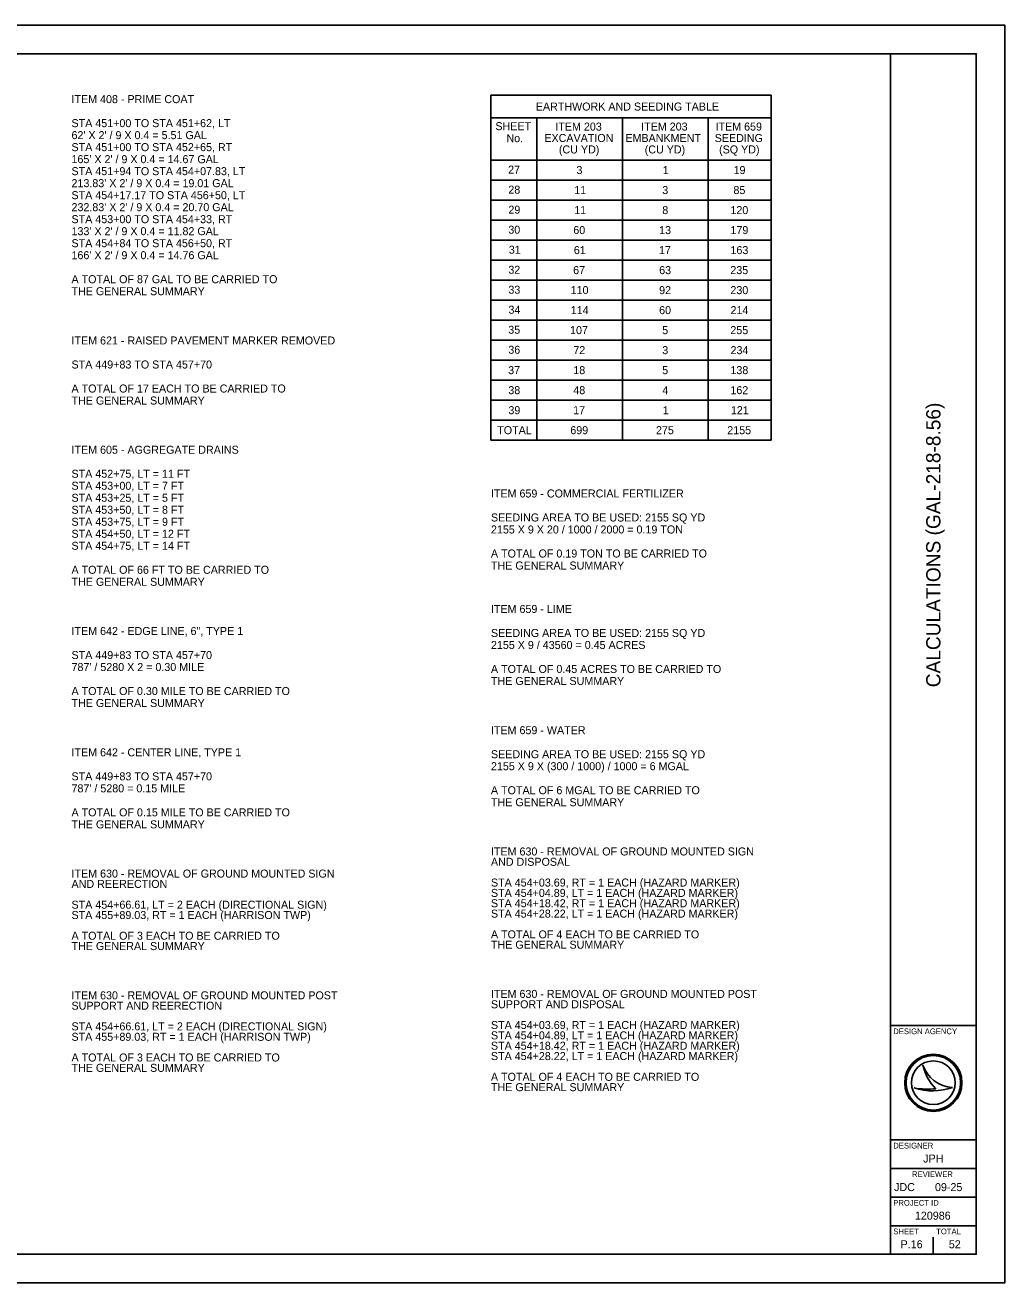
# Model space of a CAD drawing. Extents: x 0 to 126, y 0 to 48.
# Drawn here: x 50.88 to 68, y 0 to 22 of the extents above; entities that cross this region are included whole.
import ezdxf

# ---------------------------------------------------------------- set-up
doc = ezdxf.new("R2010")
doc.units = 0
for name, color, linetype in [('SH_Border', 7, 'Continuous'), ('SH_Cut_Line', 7, 'Continuous'), ('SH_Data', 7, 'Continuous'), ('TX_P_1', 7, 'Continuous')]:
    doc.layers.add(name, color=color, linetype=linetype)

msp = doc.modelspace()

# ---------------------------------------------------------------- linework, layer by layer
at = {"layer": 'SH_Border'}
for p, q in [((66, 0.5), (66, 21.5)), ((66, 4.5), (67.5, 4.5)), ((66, 2.5), (67.5, 2.5)), ((66, 2), (67.5, 2)), ((66, 1.5), (67.5, 1.5)), ((66, 1), (67.5, 1))]:
    msp.add_line(p, q, dxfattribs=at)
msp.add_lwpolyline([(35.5, 21.5), (67.5, 21.5), (67.5, 0.5), (35.5, 0.5)], close=True, dxfattribs=at)
at = {"layer": 'SH_Cut_Line'}
msp.add_lwpolyline([(34, 0), (68, 0), (68, 22), (34, 22)], close=True, dxfattribs=at)
at = {"layer": 'SH_Data'}
for p, q in [((66.567, 3.81), (66.567, 3.81)), ((66.417, 3.41), (66.417, 3.41)), ((66.75, 3.5), (66.75, 3.5)), ((67.087, 3.419), (67.087, 3.419)), ((66.375, 0.675), (66.375, 0.675)), ((66.75, 0.5), (66.75, 0.8))]:
    msp.add_line(p, q, dxfattribs=at)
for radius in [0.5, 0.477, 0.477, 0.382]:
    msp.add_circle((66.75, 3.5), radius, dxfattribs=at)
for centre, radius, start, end in [((67.116, 3.998), 0.58, 198.9257, 198.9319), ((67.347, 3.97), 0.796, 191.6379, 191.6421), ((67.116, 3.998), 0.58, 198.9319, 267.1657), ((67.347, 3.97), 0.796, 191.6421, 226.0947), ((66.739, 4.37), 1.013, 251.4576, 290.0832), ((66.648, 4.654), 1.266, 259.4964, 259.4995), ((66.739, 4.37), 1.013, 251.4527, 251.4576), ((66.648, 4.654), 1.266, 259.4995, 276.6672)]:
    msp.add_arc(centre, radius, start, end, dxfattribs=at)
at = {"layer": 'TX_P_1'}
for p, q in [((63.917, 20.776), (59.017, 20.776)), ((59.017, 20.776), (59.017, 14.74)), ((63.917, 20.776), (63.917, 14.74)), ((63.917, 20.376), (59.017, 20.376)), ((59.817, 20.376), (59.817, 14.74)), ((61.317, 20.376), (61.317, 14.74)), ((62.817, 20.376), (62.817, 14.74)), ((63.917, 19.64), (59.017, 19.64)), ((63.917, 19.29), (59.017, 19.29)), ((63.917, 18.94), (59.017, 18.94)), ((63.917, 18.59), (59.017, 18.59)), ((63.917, 18.24), (59.017, 18.24)), ((63.917, 17.89), (59.017, 17.89)), ((63.917, 17.54), (59.017, 17.54)), ((63.917, 17.19), (59.017, 17.19)), ((63.917, 16.84), (59.017, 16.84)), ((63.917, 16.49), (59.017, 16.49)), ((63.917, 16.14), (59.017, 16.14)), ((63.917, 15.79), (59.017, 15.79)), ((63.917, 15.44), (59.017, 15.44)), ((63.917, 15.09), (59.017, 15.09)), ((63.917, 14.74), (59.017, 14.74))]:
    msp.add_line(p, q, dxfattribs=at)

# ---------------------------------------------------------------- texts
at = {"layer": 'SH_Data'}
msp.add_text('CALCULATIONS (GAL-218-8.56)', height=0.25, rotation=90, dxfattribs=at).set_placement((66.875, 10.418))
for s, height, p in [('DESIGN AGENCY', 0.1, (66.05, 4.35)), ('DESIGNER', 0.1, (66.05, 2.35)), ('JPH', 0.14, (66.573, 2.105)), ('REVIEWER', 0.1, (66.378, 1.85)), ('JDC', 0.14, (66.064, 1.605)), ('09-25', 0.14, (66.779, 1.605)), ('PROJECT ID', 0.1, (66.05, 1.35)), ('120986', 0.14, (66.428, 1.105)), ('SHEET', 0.1, (66.05, 0.85)), ('TOTAL', 0.1, (66.8, 0.85)), ('P.16', 0.14, (66.178, 0.605)), ('52', 0.14, (67.021, 0.605))]:
    msp.add_text(s, height=height, dxfattribs=at).set_placement(p)
at = {"layer": 'TX_P_1'}
for s, p in [('ITEM 408 - PRIME COAT', (51.685, 20.636)), ('EARTHWORK AND SEEDING TABLE', (59.801, 20.506)), ('STA 451+00 TO STA 451+62, LT', (51.685, 20.216)), ('SHEET', (59.095, 20.163)), ('ITEM 203', (60.143, 20.156)), ('ITEM 203', (61.643, 20.156)), ('ITEM 659', (62.943, 20.156)), ("62' X 2' / 9 X 0.4 = 5.51 GAL", (51.685, 20.006)), ('No.', (59.288, 19.953)), ('EXCAVATION', (59.951, 19.956)), ('EMBANKMENT', (61.367, 19.956)), ('SEEDING', (62.928, 19.956)), ('STA 451+00 TO STA 452+65, RT', (51.685, 19.796)), ('(CU YD)', (60.205, 19.756)), ('(CU YD)', (61.705, 19.756)), ('(SQ YD)', (63.005, 19.756)), ("165' X 2' / 9 X 0.4 = 14.67 GAL", (51.685, 19.586)), ('STA 451+94 TO STA 454+07.83, LT', (51.685, 19.376)), ('27', (59.317, 19.402)), ('3', (60.512, 19.395)), ('1', (62.02, 19.395)), ('19', (63.258, 19.395)), ("213.83' X 2' / 9 X 0.4 = 19.01 GAL", (51.685, 19.166)), ('28', (59.321, 19.052)), ('11', (60.473, 19.045)), ('3', (62.012, 19.045)), ('85', (63.256, 19.045)), ('STA 454+17.17 TO STA 456+50, LT', (51.685, 18.956)), ("232.83' X 2' / 9 X 0.4 = 20.70 GAL", (51.685, 18.746)), ('29', (59.322, 18.702)), ('11', (60.473, 18.695)), ('8', (62.012, 18.695)), ('120', (63.203, 18.695)), ('STA 453+00 TO STA 454+33, RT', (51.685, 18.536)), ('30', (59.321, 18.352)), ('60', (60.457, 18.345)), ('13', (61.957, 18.345)), ('179', (63.204, 18.345)), ("133' X 2' / 9 X 0.4 = 11.82 GAL", (51.685, 18.326)), ('STA 454+84 TO STA 456+50, RT', (51.685, 18.116)), ("166' X 2' / 9 X 0.4 = 14.76 GAL", (51.685, 17.906)), ('31', (59.329, 18.002)), ('61', (60.466, 17.995)), ('17', (61.954, 17.995)), ('163', (63.204, 17.995)), ('A TOTAL OF 87 GAL TO BE CARRIED TO', (51.685, 17.486)), ('32', (59.321, 17.652)), ('67', (60.454, 17.645)), ('63', (61.958, 17.645)), ('235', (63.202, 17.645)), ('THE GENERAL SUMMARY', (51.685, 17.276)), ('33', (59.322, 17.302)), ('110', (60.41, 17.295)), ('92', (61.957, 17.295)), ('230', (63.203, 17.295)), ('34', (59.323, 16.952)), ('114', (60.412, 16.945)), ('60', (61.957, 16.945)), ('214', (63.205, 16.945)), ('35', (59.32, 16.602)), ('107', (60.4, 16.595)), ('5', (62.011, 16.595)), ('255', (63.202, 16.595)), ('ITEM 621 - RAISED PAVEMENT MARKER REMOVED', (51.685, 16.414)), ('36', (59.321, 16.252)), ('72', (60.457, 16.245)), ('3', (62.012, 16.245)), ('234', (63.205, 16.245)), ('STA 449+83 TO STA 457+70', (51.685, 15.994)), ('37', (59.318, 15.895)), ('18', (60.457, 15.895)), ('5', (62.011, 15.895)), ('138', (63.203, 15.895)), ('A TOTAL OF 17 EACH TO BE CARRIED TO', (51.685, 15.574)), ('38', (59.321, 15.545)), ('48', (60.457, 15.545)), ('4', (62.014, 15.545)), ('162', (63.203, 15.545)), ('THE GENERAL SUMMARY', (51.685, 15.364)), ('39', (59.322, 15.195)), ('17', (60.454, 15.195)), ('1', (62.02, 15.195)), ('121', (63.211, 15.195)), ('TOTAL', (59.127, 14.845)), ('699', (60.404, 14.845)), ('275', (61.902, 14.845)), ('2155', (63.148, 14.845)), ('ITEM 605 - AGGREGATE DRAINS', (51.685, 14.503)), ('STA 452+75, LT = 11 FT', (51.685, 14.083)), ('STA 453+00, LT = 7 FT', (51.685, 13.873)), ('ITEM 659 - COMMERCIAL FERTILIZER', (59.017, 13.738)), ('STA 453+25, LT = 5 FT', (51.685, 13.663)), ('STA 453+50, LT = 8 FT', (51.685, 13.453)), ('SEEDING AREA TO BE USED: 2155 SQ YD', (59.017, 13.318)), ('STA 453+75, LT = 9 FT', (51.685, 13.243)), ('2155 X 9 X 20 / 1000 / 2000 = 0.19 TON', (59.017, 13.108)), ('STA 454+50, LT = 12 FT', (51.685, 13.033)), ('STA 454+75, LT = 14 FT', (51.685, 12.823)), ('A TOTAL OF 0.19 TON TO BE CARRIED TO', (59.017, 12.688)), ('A TOTAL OF 66 FT TO BE CARRIED TO', (51.685, 12.403)), ('THE GENERAL SUMMARY', (59.017, 12.478)), ('THE GENERAL SUMMARY', (51.685, 12.193)), ('ITEM 659 - LIME', (59.017, 11.718)), ('ITEM 642 - EDGE LINE, 6", TYPE 1', (51.685, 11.332)), ('SEEDING AREA TO BE USED: 2155 SQ YD', (59.017, 11.298)), ('2155 X 9 / 43560 = 0.45 ACRES', (59.017, 11.088)), ('STA 449+83 TO STA 457+70', (51.685, 10.912)), ("787' / 5280 X 2 = 0.30 MILE", (51.685, 10.702)), ('A TOTAL OF 0.45 ACRES TO BE CARRIED TO', (59.017, 10.668)), ('THE GENERAL SUMMARY', (59.017, 10.458)), ('A TOTAL OF 0.30 MILE TO BE CARRIED TO', (51.685, 10.282)), ('THE GENERAL SUMMARY', (51.685, 10.072)), ('ITEM 659 - WATER', (59.017, 9.597)), ('ITEM 642 - CENTER LINE, TYPE 1', (51.685, 9.21)), ('SEEDING AREA TO BE USED: 2155 SQ YD', (59.017, 9.177)), ('2155 X 9 X (300 / 1000) / 1000 = 6 MGAL', (59.017, 8.967)), ('STA 449+83 TO STA 457+70', (51.685, 8.79)), ("787' / 5280 = 0.15 MILE", (51.685, 8.58)), ('A TOTAL OF 6 MGAL TO BE CARRIED TO', (59.017, 8.547)), ('THE GENERAL SUMMARY', (59.017, 8.337)), ('A TOTAL OF 0.15 MILE TO BE CARRIED TO', (51.685, 8.16)), ('THE GENERAL SUMMARY', (51.685, 7.95)), ('ITEM 630 - REMOVAL OF GROUND MOUNTED SIGN', (59.017, 7.476)), ('AND DISPOSAL', (59.017, 7.295)), ('AND REERECTION', (51.685, 6.908)), ('ITEM 630 - REMOVAL OF GROUND MOUNTED SIGN', (51.685, 7.089)), ('STA 454+03.69, RT = 1 EACH (HAZARD MARKER)', (59.017, 6.932)), ('STA 454+04.89, LT = 1 EACH (HAZARD MARKER)', (59.017, 6.751)), ('STA 454+66.61, LT = 2 EACH (DIRECTIONAL SIGN)', (51.685, 6.545)), ('STA 454+18.42, RT = 1 EACH (HAZARD MARKER)', (59.017, 6.57)), ('STA 455+89.03, RT = 1 EACH (HARRISON TWP)', (51.685, 6.364)), ('STA 454+28.22, LT = 1 EACH (HAZARD MARKER)', (59.017, 6.389)), ('A TOTAL OF 4 EACH TO BE CARRIED TO', (59.017, 6.026)), ('A TOTAL OF 3 EACH TO BE CARRIED TO', (51.685, 6.002)), ('THE GENERAL SUMMARY', (51.685, 5.821)), ('THE GENERAL SUMMARY', (59.017, 5.845)), ('ITEM 630 - REMOVAL OF GROUND MOUNTED POST', (51.685, 4.959)), ('ITEM 630 - REMOVAL OF GROUND MOUNTED POST', (59.017, 4.984)), ('SUPPORT AND REERECTION', (51.685, 4.778)), ('SUPPORT AND DISPOSAL', (59.017, 4.803)), ('STA 454+66.61, LT = 2 EACH (DIRECTIONAL SIGN)', (51.685, 4.416)), ('STA 454+03.69, RT = 1 EACH (HAZARD MARKER)', (59.017, 4.44)), ('STA 454+04.89, LT = 1 EACH (HAZARD MARKER)', (59.017, 4.259)), ('STA 455+89.03, RT = 1 EACH (HARRISON TWP)', (51.685, 4.234)), ('STA 454+18.42, RT = 1 EACH (HAZARD MARKER)', (59.017, 4.078)), ('A TOTAL OF 3 EACH TO BE CARRIED TO', (51.685, 3.872)), ('STA 454+28.22, LT = 1 EACH (HAZARD MARKER)', (59.017, 3.897)), ('THE GENERAL SUMMARY', (51.685, 3.691)), ('A TOTAL OF 4 EACH TO BE CARRIED TO', (59.017, 3.534)), ('THE GENERAL SUMMARY', (59.017, 3.353))]:
    msp.add_text(s, height=0.14, dxfattribs=at).set_placement(p)

doc.saveas('drawing.dxf')
